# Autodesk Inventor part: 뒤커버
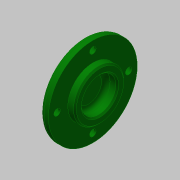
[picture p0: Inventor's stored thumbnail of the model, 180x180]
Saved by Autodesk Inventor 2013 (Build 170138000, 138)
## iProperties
Created: 2015-12
Part Number: 뒤커버
Document SubType Name: Modeling
Designer: mdu
Density: 2.71 g/cm^3
Material: 알루미늄 6061
Author: mdu
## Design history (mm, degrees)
sketch "스케치1"
  geometry: L1 (-7, 0)-(7, 0); L2 (-7, 0)-(-7, 15.539); L3 (-7, 15.539)-(-4, 18.5); L4 (-4, 18.5)-(-4, 31); L5 (-4, 31)-(2, 31); L6 (2, 31)-(2, 17.5); L7 (2, 17.5)-(7, 17.5); L8 (7, 17.5)-(7, 0); 2 further points
  constraints: 16 end point, 4 parallel, 2 perpendicular, 1 coincident, 1 horizontal, 1 midpoint
  dimensions: "d0" = 14 distance of L1.start L1.end; "d1" = 62 diameter of L5 L1; "d2" = 35 diameter of L7 L1; "d3" = 37 diameter of L3.end L1; "d4" = 3 distance between parallel lines of L4 L2; "d5" = 6 distance of L4.end L5.end
revolve "회전1" sketch "스케치1" stored, may be unused: angle "d6" = 90 deg
sketch "스케치2" dims "d32" = 50
  geometry: 3 further points
  constraints: 2 vertical alignment, 1 coincident, 2 other
hole "구멍1" sketch "스케치2" at (0, 25) diameter "d8" = 4.5; stored, may be unused: countersink angle "d12" = 90 deg, drill point angle "d14" = 118 deg; dims "d9" = 6, "d10" = 8, "d11" = 4.4, "d13" = 8
hole "구멍2" diameter "d20" = 24; stored, may be unused: countersink angle "d24" = 90 deg, drill point angle "d26" = 0 deg; dims "d18" = 10, "d19" = 10, "d21" = 6, "d22" = 8, "d23" = 4.4, "d25" = 8
fillet "모깎기1" dims "d27" = 3
fillet "모깎기2" dims "d28" = 3
chamfer "모따기1" distance "d29" = 1; stored, may be unused: second distance "d30" = 2, angle "d31" = 45 deg
node "솔리드1"
pattern_circular "원형 패턴1" dims angle "d16" = 360 deg
